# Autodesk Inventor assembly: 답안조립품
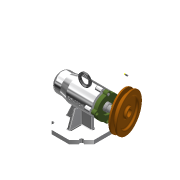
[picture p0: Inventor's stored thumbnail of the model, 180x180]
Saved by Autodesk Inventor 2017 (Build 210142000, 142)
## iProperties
Created: 2019-12
Part Number: 답안조립품
Document SubType Name: Assembly
Designer: 5-07-le-1
Author: 5-07-le-1
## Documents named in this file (12)
- C:\Users\5-07-le-1\Desktop\답안조립품.iam
- C:\Users\5-07-le-1\Desktop\491204V1009\부품1.ipt
- C:\Users\5-07-le-1\Desktop\491204V1009-----\V벨트풀리.ipt
- C:\Users\5-07-le-1\Desktop\491204V1009-----\멈춤나사 M3.ipt
- C:\Users\5-07-le-1\Desktop\491204V1009-----\베어링 6004.ipt
- C:\Users\5-07-le-1\Desktop\491204V1009-----\베어링 51202.ipt
- C:\Users\5-07-le-1\Desktop\491204V1009-----\볼트 M4.ipt
- C:\Users\5-07-le-1\Desktop\491204V1009-----\어댑터슬리브.ipt
- C:\Users\5-07-le-1\Desktop\491204V1009-----\오일 실.ipt
- C:\Users\5-07-le-1\Desktop\491204V1009-----\축.ipt
- C:\Users\5-07-le-1\Desktop\491204V1009-----\커버.ipt
- C:\Users\5-07-le-1\Desktop\491204V1009-----\키 5 x 5 x 16.ipt
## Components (1 placed, 1 different names)
1. V벨트풀리:1
